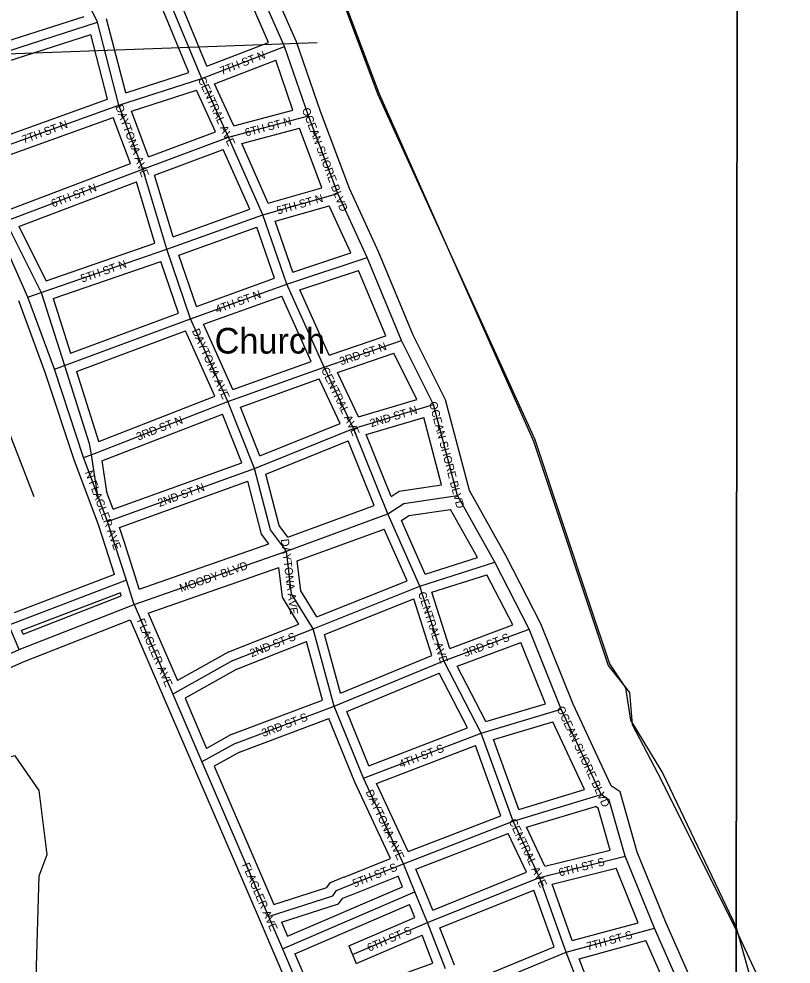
# Model space of a CAD drawing. Extents: x 457167 to 656239, y 1787309 to 1969297.
# Drawn here: x 614226 to 616636, y 1869724 to 1872675 of the extents above; entities that cross this region are included whole.
import ezdxf

# ---------------------------------------------------------------- set-up
doc = ezdxf.new("R2010")
doc.units = 0
for name, color, linetype in [('Level 1', 7, 'Continuous'), ('Level 22', 7, 'Continuous'), ('Level 23', 7, 'Continuous'), ('Level 31', 7, 'Continuous'), ('Level 32', 7, 'Continuous'), ('Level 34', 7, 'Continuous'), ('Level 5', 7, 'Continuous'), ('Level 57', 7, 'Continuous'), ('Level 63', 7, 'Continuous'), ('Level 7', 7, 'Continuous'), ('Level 8', 7, 'Continuous')]:
    doc.layers.add(name, color=color, linetype=linetype)

msp = doc.modelspace()

# ---------------------------------------------------------------- linework, layer by layer
at = {"layer": 'Level 1'}
msp.add_line((615156.706, 1872600.383), (611305.7, 1872459.876), dxfattribs=at)
at = {"layer": 'Level 22'}
for p, q in [((615055.016, 1872588.769), (614889.667, 1872964.947)), ((615129.865, 1872371.961), (615055.016, 1872588.769)), ((615221.233, 1872130.045), (615129.865, 1872371.961)), ((615312.647, 1871929.947), (615221.233, 1872130.045)), ((615420.545, 1871671.286), (615312.647, 1871929.947)), ((615520.234, 1871471.181), (615420.545, 1871671.286)), ((615594.696, 1871187.466), (615520.234, 1871471.181)), ((615711.243, 1870978.978), (615594.696, 1871187.466)), ((615060.91, 1871013.146), (615377.95, 1871129.521)), ((614585.675, 1870847.131), (615060.91, 1871013.146)), ((615819.2, 1870770.136), (615711.243, 1870978.978)), ((614226.92, 1870706.082), (614585.675, 1870847.131)), ((615918.839, 1870519.849), (615819.2, 1870770.136)), ((613943.273, 1870581.678), (614226.92, 1870706.082)), ((616043.281, 1870253.173), (615918.839, 1870519.849)), ((616209.565, 1869835.908), (616118.167, 1870061.095)), ((616323.838, 1869577.244), (616209.565, 1869835.908))]:
    msp.add_line(p, q, dxfattribs=at)
for points in [[(615377.95, 1871129.521), (615427.94, 1871162.557), (615594.696, 1871187.466)], [(616118.167, 1870061.095), (616068.4, 1870236.419), (616043.281, 1870253.173)]]:
    msp.add_lwpolyline(points, dxfattribs=at)
at = {"layer": 'Level 23'}
for p, q in [((615092.293, 1872603.367), (614926.286, 1872981.043)), ((615005.572, 1872601.849), (614863.518, 1872925.029)), ((615167.489, 1872385.557), (615092.293, 1872603.367)), ((615081.276, 1872390.126), (615027.469, 1872545.985)), ((615258.177, 1872145.44), (615167.489, 1872385.557)), ((615171.974, 1872147.252), (615101.65, 1872333.452)), ((615349.307, 1871945.962), (615258.176, 1872145.439)), ((615261.91, 1871944.741), (615194.914, 1872091.392)), ((615456.945, 1871687.923), (615349.307, 1871945.962)), ((615371.055, 1871686.022), (615286.15, 1871889.563)), ((615557.875, 1871485.324), (615456.945, 1871687.923)), ((615467.748, 1871486.829), (615395.873, 1871631.103)), ((615632.094, 1871202.541), (615557.875, 1871485.323)), ((615544.686, 1871220.44), (615489.501, 1871430.705)), ((615746.477, 1870997.926), (615632.095, 1871202.541)), ((615065.361, 1871057.39), (615334.78, 1871156.286)), ((615657.423, 1870993.275), (615573.267, 1871143.82)), ((615094.84, 1870982.99), (615365.949, 1871082.506)), ((614601.863, 1870895.157), (615006.18, 1871036.398)), ((615855.635, 1870786.757), (615746.477, 1870997.925)), ((614629.923, 1870820.217), (615036.918, 1870962.393)), ((615767.554, 1870782.933), (615686.569, 1870939.598)), ((614239.238, 1870753.906), (614545.527, 1870874.328)), ((614242.275, 1870669.138), (614573.564, 1870799.388)), ((615955.575, 1870535.716), (615855.635, 1870786.757)), ((615869.193, 1870536.404), (615792.796, 1870728.305)), ((613957.77, 1870544.356), (614242.275, 1870669.137)), ((616074.793, 1870280.236), (615955.575, 1870535.716)), ((615991.769, 1870268.966), (615892.894, 1870480.851)), ((616246.4, 1869851.515), (616156.051, 1870074.116)), ((616159.306, 1869853.371), (616090.344, 1870023.281)), ((616362.606, 1869588.472), (616246.4, 1869851.515)), ((616273.378, 1869592.475), (616182.773, 1869797.565))]:
    msp.add_line(p, q, dxfattribs=at)
for points in [[(615388.198, 1871184.239), (615413.275, 1871200.811), (615544.686, 1871220.439)], [(615419.75, 1871109.199), (615442.607, 1871124.304), (615573.267, 1871143.82)], [(616156.051, 1870074.115), (616102.857, 1870261.519), (616074.793, 1870280.236)], [(616071.125, 1870080.332), (616033.945, 1870211.318), (616025.994, 1870216.621)]]:
    msp.add_lwpolyline(points, dxfattribs=at)
at = {"layer": 'Level 31'}
for p, q in [((614796.55, 1872489.057), (614633.768, 1872882.688)), ((614471.575, 1872664.691), (614394.438, 1872823.321)), ((613979.505, 1872507.067), (614471.575, 1872664.691)), ((614538.101, 1872406.074), (614471.575, 1872664.691)), ((614796.55, 1872489.057), (615055.016, 1872588.769)), ((614538.101, 1872406.074), (614796.55, 1872489.057)), ((614879.707, 1872305.695), (614796.55, 1872489.057)), ((614079.109, 1872240.412), (614538.101, 1872406.074)), ((614612.649, 1872205.993), (614538.101, 1872406.074)), ((614879.707, 1872305.695), (615129.865, 1872371.961)), ((614612.649, 1872205.993), (614879.707, 1872305.695)), ((614987.619, 1872063.76), (614879.707, 1872305.695)), ((614184.52, 1872043.203), (614612.649, 1872205.993)), ((614687.459, 1871955.731), (614612.649, 1872205.993)), ((614987.619, 1872063.76), (615221.233, 1872130.045)), ((614687.459, 1871955.731), (614987.619, 1872063.76)), ((615062.15, 1871846.952), (614987.619, 1872063.76)), ((614253.615, 1871806.401), (614153.961, 1872031.602)), ((614184.52, 1872043.203), (614295.63, 1871820.536)), ((614295.63, 1871820.536), (614687.459, 1871955.731)), ((614761.988, 1871738.923), (614687.459, 1871955.731)), ((615062.15, 1871846.952), (615312.647, 1871929.947)), ((614761.988, 1871738.923), (615062.15, 1871846.952)), ((615178.636, 1871588.281), (615062.15, 1871846.952)), ((614253.615, 1871806.401), (614295.63, 1871820.536)), ((614336.724, 1871581.22), (614253.615, 1871806.401)), ((614295.63, 1871820.536), (614368.237, 1871592.821)), ((614368.237, 1871592.821), (614761.988, 1871738.923)), ((614878.155, 1871480.251), (614761.988, 1871738.923)), ((615178.636, 1871588.281), (615420.545, 1871671.286)), ((614336.724, 1871581.22), (614368.237, 1871592.821)), ((614427.733, 1871305.848), (614336.724, 1871581.22)), ((614878.155, 1871480.251), (615178.636, 1871588.281)), ((615270.061, 1871396.546), (615178.636, 1871588.281)), ((614451.288, 1871314.549), (614878.155, 1871480.251)), ((614961.287, 1871271.799), (614878.155, 1871480.251)), ((615270.061, 1871396.546), (615520.234, 1871471.181)), ((614961.287, 1871271.799), (615270.061, 1871396.546)), ((615377.95, 1871129.521), (615270.061, 1871396.546)), ((614427.733, 1871305.848), (614451.288, 1871314.549)), ((614470.241, 1871192.347), (614427.733, 1871305.848)), ((614451.288, 1871314.549), (614470.241, 1871192.347)), ((614502.599, 1871105.767), (614961.287, 1871271.799)), ((614502.599, 1871105.767), (614470.241, 1871192.347)), ((615477.613, 1870904.325), (615377.95, 1871129.521)), ((614525.746, 1871034.106), (614502.599, 1871105.767)), ((614561.577, 1870922.794), (614525.746, 1871034.106)), ((615477.613, 1870904.325), (615711.243, 1870978.978)), ((614561.577, 1870922.794), (614194.55, 1870782.481)), ((614585.675, 1870847.131), (614561.577, 1870922.794)), ((615144.007, 1870771.239), (615477.613, 1870904.325)), ((615552.132, 1870670.792), (615477.613, 1870904.325)), ((614585.675, 1870847.131), (614706.273, 1870567.001)), ((614226.92, 1870706.082), (614194.55, 1870782.481)), ((614893.802, 1870671.881), (615144.007, 1870771.239)), ((615210.242, 1870529.351), (615144.007, 1870771.239)), ((615552.132, 1870670.792), (615819.2, 1870770.136)), ((614893.802, 1870671.881), (614706.273, 1870567.001)), ((615210.242, 1870529.351), (615552.132, 1870670.792)), ((615668.661, 1870445.576), (615552.132, 1870670.792)), ((614706.273, 1870567.001), (614797.357, 1870355.265)), ((614901.47, 1870413.331), (615210.242, 1870529.351)), ((615301.633, 1870304.162), (615210.242, 1870529.351)), ((615668.661, 1870445.576), (615918.839, 1870519.849)), ((615301.633, 1870304.162), (615668.661, 1870445.576)), ((615768.274, 1870170.2), (615668.661, 1870445.576)), ((614901.47, 1870413.331), (614797.357, 1870355.265)), ((614797.357, 1870355.265), (614941.761, 1870019.473)), ((615426.072, 1870037.484), (615301.633, 1870304.162)), ((615768.274, 1870170.2), (616043.281, 1870253.173)), ((615426.072, 1870037.484), (615768.274, 1870170.2)), ((615851.131, 1869994.839), (615768.274, 1870170.2)), ((615851.131, 1869994.839), (616118.167, 1870061.095)), ((615252.58, 1869968.221), (615426.072, 1870037.484)), ((615461.931, 1869949.81), (615426.072, 1870037.484)), ((614941.761, 1870019.473), (615004.697, 1869873.056)), ((615217.564, 1869954.441), (615252.58, 1869968.221)), ((615500.965, 1869853.768), (615851.131, 1869994.839)), ((615934.245, 1869761.297), (615851.131, 1869994.839)), ((615004.697, 1869873.056), (615205.454, 1869937.728)), ((615048.367, 1869771.459), (615461.931, 1869949.81)), ((615205.454, 1869937.728), (615217.564, 1869954.441)), ((615500.965, 1869853.768), (615461.931, 1869949.81)), ((615004.697, 1869873.056), (615048.367, 1869771.459)), ((615267.3, 1869754.026), (615500.965, 1869853.768)), ((615557.445, 1869709.708), (615500.965, 1869853.768)), ((615934.245, 1869761.297), (616209.565, 1869835.908)), ((615048.367, 1869771.459), (615141.71, 1869554.166)), ((615592.35, 1869620.216), (615934.245, 1869761.297)), ((616042.135, 1869486.275), (615934.245, 1869761.297))]:
    msp.add_line(p, q, dxfattribs=at)
for points in [[(614368.237, 1871592.821), (614445.6, 1871349.827), (614451.288, 1871314.549)], [(615060.91, 1871013.146), (615011.03, 1871080.109), (614961.287, 1871271.799)], [(615144.007, 1870771.239), (615077.309, 1870879.675), (615060.91, 1871013.146)]]:
    msp.add_lwpolyline(points, dxfattribs=at)
at = {"layer": 'Level 32'}
for p, q in [((614813.08, 1872527.588), (614673.925, 1872864.084)), ((614756.388, 1872507.67), (614615.916, 1872847.349)), ((613993.671, 1872543.107), (614429.456, 1872682.701)), ((614559.228, 1872444.366), (614499.877, 1872675.091)), ((614020.864, 1872488.813), (614450.442, 1872626.419)), ((614502.247, 1872425.028), (614450.442, 1872626.419)), ((614813.079, 1872527.588), (615005.572, 1872601.849)), ((614836.998, 1872472.505), (615027.469, 1872545.985)), ((614559.227, 1872444.366), (614756.387, 1872507.67)), ((614577.18, 1872387.112), (614780.269, 1872452.32)), ((614839.115, 1872322.563), (614780.268, 1872452.32)), ((614896.55, 1872341.19), (614836.998, 1872472.505)), ((614101.22, 1872280.287), (614502.247, 1872425.029)), ((614630.279, 1872244.597), (614577.18, 1872387.111)), ((614896.55, 1872341.19), (615081.276, 1872390.126)), ((614127.865, 1872226.114), (614520.355, 1872367.774)), ((614574.131, 1872223.443), (614520.355, 1872367.775)), ((614921.465, 1872285.721), (615101.65, 1872333.452)), ((614630.28, 1872244.598), (614839.115, 1872322.563)), ((614649.427, 1872187.701), (614863.79, 1872267.729)), ((614947.058, 1872081.046), (614863.79, 1872267.729)), ((615004.43, 1872099.713), (614921.465, 1872285.721)), ((614201.58, 1872081.786), (614574.131, 1872223.442)), ((614707.123, 1871994.692), (614649.427, 1872187.701)), ((614226.16, 1872026.941), (614593.147, 1872166.481)), ((614650.474, 1871974.705), (614593.147, 1872166.481)), ((615004.43, 1872099.713), (615171.975, 1872147.252)), ((615026.29, 1872043.547), (615194.914, 1872091.392)), ((614707.124, 1871994.692), (614947.058, 1872081.046)), ((615080.875, 1871884.761), (615026.29, 1872043.547)), ((614226.161, 1872026.94), (614310.723, 1871857.478)), ((614725.442, 1871937.516), (614969.141, 1872025.224)), ((615024.165, 1871865.165), (614969.141, 1872025.225)), ((614310.723, 1871857.479), (614650.474, 1871974.705)), ((615080.875, 1871884.761), (615261.91, 1871944.741)), ((614333.113, 1871801.732), (614668.85, 1871917.573)), ((614724.097, 1871756.861), (614668.851, 1871917.573)), ((614780.464, 1871777.457), (614725.442, 1871937.516)), ((615103.164, 1871828.936), (615286.15, 1871889.563)), ((614780.465, 1871777.457), (615024.165, 1871865.165)), ((615194.763, 1871625.531), (615103.164, 1871828.936)), ((614333.113, 1871801.731), (614387.27, 1871631.881)), ((614802.625, 1871721.663), (615046.192, 1871809.323)), ((615137.962, 1871605.538), (615046.192, 1871809.324)), ((614308.4, 1871571.315), (614225.797, 1871795.126)), ((614387.27, 1871631.881), (614724.097, 1871756.862)), ((614894.142, 1871517.88), (614802.625, 1871721.664)), ((614405.505, 1871574.65), (614746.115, 1871701.034)), ((614837.842, 1871496.783), (614746.115, 1871701.033)), ((615194.763, 1871625.532), (615371.055, 1871686.022)), ((615220.195, 1871570.824), (615395.873, 1871631.102)), ((614894.142, 1871517.88), (615137.962, 1871605.538)), ((614399.431, 1871295.876), (614308.4, 1871571.315)), ((615286.088, 1871432.635), (615220.195, 1871570.824)), ((614917.522, 1871462.524), (615163.24, 1871550.865)), ((615229.256, 1871412.416), (615163.24, 1871550.865)), ((614475.002, 1871355.936), (614837.842, 1871496.784)), ((615286.089, 1871432.635), (615467.747, 1871486.829)), ((614484.63, 1871295.31), (614861.3, 1871441.526)), ((614921.944, 1871289.462), (614861.3, 1871441.526)), ((614977.989, 1871310.903), (614917.521, 1871462.524)), ((614977.989, 1871310.901), (615229.255, 1871412.416)), ((615310.225, 1871377.221), (615489.501, 1871430.705)), ((614996.94, 1871253.846), (615253.484, 1871357.492)), ((615334.78, 1871156.285), (615253.483, 1871357.491)), ((615388.198, 1871184.24), (615310.225, 1871377.221)), ((614442.146, 1871181.825), (614399.43, 1871295.876)), ((614484.63, 1871295.31), (614499.416, 1871199.976)), ((614520.305, 1871144.081), (614921.944, 1871289.462)), ((614540.051, 1871087.418), (614940.522, 1871232.376)), ((614474.259, 1871095.899), (614442.14, 1871181.845)), ((614520.305, 1871144.081), (614499.416, 1871199.976)), ((614497.198, 1871024.883), (614474.259, 1871095.899)), ((614554.295, 1871043.326), (614540.051, 1871087.418)), ((615494.143, 1870941.101), (615419.75, 1871109.198)), ((615437.578, 1870920.653), (615365.95, 1871082.506)), ((614590.134, 1870931.986), (614554.304, 1871043.297)), ((614524.307, 1870940.663), (614497.189, 1871024.912)), ((615494.143, 1870941.101), (615657.423, 1870993.275)), ((614524.307, 1870940.663), (614210.875, 1870820.84)), ((615515.31, 1870884.875), (615686.57, 1870939.599)), ((614601.863, 1870895.157), (614590.162, 1870931.897)), ((615156.335, 1870808.456), (615437.578, 1870920.653)), ((614542.628, 1870883.431), (614234.3, 1870765.56)), ((614545.526, 1870874.328), (614542.628, 1870883.431)), ((615571.15, 1870709.875), (615515.31, 1870884.875)), ((615180.022, 1870753.306), (615458.82, 1870864.527)), ((615515.16, 1870687.963), (615458.82, 1870864.527)), ((614573.565, 1870799.389), (614678.716, 1870555.137)), ((614629.923, 1870820.216), (614720.669, 1870609.426)), ((614239.237, 1870753.906), (614234.3, 1870765.559)), ((614880.886, 1870699.031), (615099.742, 1870785.94)), ((615571.151, 1870709.876), (615767.555, 1870782.933)), ((615230.195, 1870570.071), (615180.021, 1870753.306)), ((614906.715, 1870644.729), (615123.925, 1870730.984)), ((615174.081, 1870547.811), (615123.925, 1870730.984)), ((615594.346, 1870654.486), (615792.796, 1870728.305)), ((614880.886, 1870699.031), (614720.669, 1870609.426)), ((615230.196, 1870570.071), (615515.161, 1870687.963)), ((614906.715, 1870644.729), (614744.516, 1870554.015)), ((615683.905, 1870481.396), (615594.346, 1870654.486)), ((615249.245, 1870513.02), (615538.145, 1870632.539)), ((615626.627, 1870461.531), (615538.145, 1870632.539)), ((614678.714, 1870555.145), (614769.799, 1870343.41)), ((614744.515, 1870554.015), (614811.777, 1870397.657)), ((614888.816, 1870440.623), (615174.081, 1870547.811)), ((615683.905, 1870481.396), (615869.193, 1870536.405)), ((615318.347, 1870342.752), (615249.245, 1870513.02)), ((614914.122, 1870386.036), (615193.434, 1870490.986)), ((615274.122, 1870292.171), (615193.434, 1870490.986)), ((615707.692, 1870425.869), (615892.895, 1870480.851)), ((614888.816, 1870440.623), (614811.778, 1870397.657)), ((615318.348, 1870342.751), (615626.627, 1870461.53)), ((615786.816, 1870207.131), (615707.692, 1870425.869)), ((614914.122, 1870386.036), (614835.61, 1870342.248)), ((615342.409, 1870287.722), (615650.867, 1870406.571)), ((615730.087, 1870187.567), (615650.867, 1870406.571)), ((614769.797, 1870343.413), (614914.201, 1870007.621)), ((614835.61, 1870342.248), (614969.321, 1870031.324)), ((615385.458, 1870053.572), (615274.122, 1870292.171)), ((615441.39, 1870075.601), (615342.41, 1870287.722)), ((615786.816, 1870207.131), (615991.769, 1870268.966)), ((615810.273, 1870151.535), (616025.994, 1870216.621)), ((615441.39, 1870075.602), (615730.088, 1870187.567)), ((615867.757, 1870029.874), (615810.273, 1870151.535)), ((615465.405, 1870020.561), (615753.08, 1870132.129)), ((615810.418, 1870010.78), (615753.08, 1870132.129)), ((615867.756, 1870029.874), (616071.124, 1870080.332)), ((614969.324, 1870031.32), (615021.48, 1869909.981)), ((615241.456, 1869996.082), (615385.458, 1870053.572)), ((614914.199, 1870007.626), (614978.626, 1869857.737)), ((615198.416, 1869979.146), (615241.595, 1869996.136)), ((615263.703, 1869940.357), (615409.565, 1869998.59)), ((615423.019, 1869965.699), (615409.566, 1869998.591)), ((615489.699, 1869961.166), (615465.405, 1870020.561)), ((615517.495, 1869892.771), (615810.418, 1870010.78)), ((615890.499, 1869973.696), (616090.345, 1870023.281)), ((615064.068, 1869810.901), (615423.019, 1869965.7)), ((615186.916, 1869963.274), (615198.416, 1869979.146)), ((615953.199, 1869797.516), (615890.499, 1869973.696)), ((615021.48, 1869909.981), (615186.916, 1869963.274)), ((615236.71, 1869929.736), (615263.565, 1869940.303)), ((615517.495, 1869892.771), (615489.724, 1869961.105)), ((615539.743, 1869837.046), (615833.347, 1869955.33)), ((615896.408, 1869778.137), (615833.347, 1869955.33)), ((615045.28, 1869854.611), (615223.99, 1869912.181)), ((615087.755, 1869755.774), (615445.674, 1869910.126)), ((615223.99, 1869912.181), (615236.71, 1869929.736)), ((615462.07, 1869869.784), (615445.675, 1869910.126)), ((614978.626, 1869857.737), (615021.472, 1869758.055)), ((615045.28, 1869854.611), (615064.068, 1869810.901)), ((615255.521, 1869781.616), (615462.07, 1869869.784)), ((615953.198, 1869797.516), (616159.306, 1869853.37)), ((615585.376, 1869720.658), (615539.743, 1869837.046)), ((615279.078, 1869726.433), (615484.315, 1869814.041)), ((615518.247, 1869727.494), (615484.315, 1869814.041)), ((615974.396, 1869741.095), (616182.773, 1869797.565)), ((615255.521, 1869781.616), (615279.078, 1869726.433)), ((615609.183, 1869659.616), (615896.408, 1869778.138)), ((615021.47, 1869758.061), (615114.145, 1869542.326)), ((615087.755, 1869755.774), (615157.135, 1869594.266)), ((616059.76, 1869523.491), (615974.396, 1869741.095)), ((615294.229, 1869646.945), (615518.248, 1869727.494))]:
    msp.add_line(p, q, dxfattribs=at)
for points in [[(614405.505, 1871574.65), (614474.863, 1871356.804), (614475.002, 1871355.935)], [(615065.36, 1871057.39), (615038.594, 1871093.325), (614996.939, 1871253.846)], [(615006.18, 1871036.398), (614983.465, 1871066.894), (614940.522, 1871232.376)], [(615156.335, 1870808.456), (615106.288, 1870889.823), (615094.84, 1870982.99)], [(615099.743, 1870785.94), (615048.329, 1870869.526), (615036.918, 1870962.393)]]:
    msp.add_lwpolyline(points, dxfattribs=at)
at = {"layer": 'Level 5'}
for points in [[(612905.535, 1878220.299), (612930.405, 1878095.227), (613329.636, 1877261.166), (613487.7, 1876935.891), (613770.349, 1876202.001), (613820.27, 1876118.571), (614119.628, 1875384.651), (614460.568, 1874592.35), (614660.014, 1874008.611), (615159.077, 1872949.378), (615350.262, 1872440.641), (615832.625, 1871356.426), (616065.282, 1870655.916), (616131.874, 1870572.496), (616140.115, 1870472.424), (616231.657, 1870297.261), (616464.543, 1869830.206), (616464.765, 1869829.726)], [(614273.545, 1871182.996), (614082.329, 1871675.032), (613965.975, 1872008.616), (613916.065, 1872117.058), (613874.414, 1872142.098), (613640.93, 1872067.336)], [(616464.765, 1869829.726), (616689.139, 1869346.469), (616772.201, 1869079.605), (616996.757, 1868579.198), (617412.528, 1867586.725), (617512.271, 1867311.531), (617753.467, 1866786.084)]]:
    msp.add_lwpolyline(points, dxfattribs=at)
at = {"layer": 'Level 63'}
for points in [[(576611.219, 1832825.663), (616425.226, 1832761.92), (616473.71, 1878215.526), (576708.29, 1878279.4), (576611.219, 1832825.663)], [(616425.226, 1832761.92), (656239.136, 1832740.786), (656239.03, 1878194.373), (616473.71, 1878215.526), (616425.226, 1832761.92)]]:
    msp.add_lwpolyline(points, dxfattribs=at)
at = {"layer": 'Level 7'}
msp.add_lwpolyline([(614280.274, 1869682.472), (614288.972, 1869999.247), (614314.051, 1870065.908), (614289.23, 1870266.011), (614214.339, 1870374.442), (613864.114, 1870299.78), (613088.545, 1870025.531), (612996.784, 1869958.94), (612979.945, 1869800.547)], dxfattribs=at)
at = {"layer": 'Level 8'}
for points in [[(612954.764, 1878221.178), (612955.405, 1878219.799), (612971.406, 1878069.796), (613328.416, 1877267.786), (613486.42, 1876942.781), (613768.429, 1876208.771), (613809.43, 1876140.771), (613818.43, 1876125.771), (614109.438, 1875382.761), (614458.448, 1874590.75), (614657.454, 1874006.741), (615155.467, 1872946.727), (615346.472, 1872438.721), (615836.485, 1871361.706), (616007.49, 1870847.699), (616069.492, 1870661.696), (616119.494, 1870586.696)], [(616119.494, 1870586.696), (616135.495, 1870485.694), (616235.497, 1870319.691), (616464.503, 1869839.686), (616464.775, 1869838.715)], [(616464.775, 1869838.715), (616745.512, 1868837.671), (619996.599, 1860769.559)]]:
    msp.add_lwpolyline(points, dxfattribs=at)

# ---------------------------------------------------------------- texts
at = {"layer": 'Level 34'}
for s, height, rotation, p in [('7TH ST N', 25, 21.095419, (614859.17, 1872499.817)), ('CENTRAL AVE', 25, 294.394614, (614784.012, 1872486.441)), ('DAYTONA AVE', 25, 290.434292, (614526.549, 1872401.28)), ('OCEAN SHORE BLVD', 25, 290.690375, (615108.771, 1872392.436)), ('7TH ST N', 25, 19.845497, (614241.155, 1872285.61)), ('6TH ST N', 25, 14.836683, (614934.917, 1872307.389)), ('6TH ST N', 25, 20.818186, (614332.371, 1872086.049)), ('5TH ST N', 25, 15.840594, (615034.664, 1872064.115)), ('5TH ST N', 25, 19.035983, (614423.718, 1871851.508)), ('4TH ST N', 24.9992, 19.793575, (614844.291, 1871755.26)), ('DAYTONA AVE', 25, 294.183961, (614765.121, 1871701.436)), ('3RD ST N', 25, 18.938244, (615231.701, 1871593.275)), ('CENTRAL AVE', 25, 295.492936, (615168.535, 1871580.424)), ('OCEAN SHORE BLVD', 25, 284.705722, (615505.797, 1871476.948)), ('2ND ST N', 25, 16.611019, (615325.832, 1871400.141)), ('3RD ST N', 25, 21.215083, (614598.336, 1871358.222)), ('N FLAGLER AVE', 25, 290.491861, (614431.71, 1871259.742)), ('2ND ST N', 25, 19.898472, (614664.676, 1871151.141)), ('DAYTONA AVE', 25, 277.003875, (615043.741, 1871050.392)), ('MOODY BLVD', 25, 19.255539, (614732.414, 1870885.151)), ('CENTRAL AVE', 25, 287.697175, (615471.512, 1870882.327)), ('FLAGLER AVE', 25, 293.291928, (614593.768, 1870796.721)), ('2ND ST S', 25, 21.657972, (614952.825, 1870681.871)), ('3RD ST S', 25, 20.403922, (615618.733, 1870682.23)), ('OCEAN SHORE BLVD', 25, 295.015433, (615903.806, 1870522.506)), ('3RD ST S', 25, 20.593258, (614989.05, 1870432.886)), ('4TH ST S', 25, 21.071125, (615418.223, 1870335.689)), ('DAYTONA AVE', 25, 295.014608, (615307.576, 1870261.866)), ('CENTRAL AVE', 25, 295.290514, (615754.2, 1870170.726)), ('6TH ST S', 25, 13.934267, (615914.294, 1869997.631)), ('FLAGLER AVE', 25, 293.259567, (614921.82, 1870034.214)), ('5TH ST S', 25, 21.763011, (615273.32, 1869963.041)), ('6TH ST S', 25, 23.115367, (615319.518, 1869762.726)), ('7TH ST S', 25, 15.162533, (616001.608, 1869766.602))]:
    msp.add_text(s, height=height, rotation=rotation, dxfattribs=at).set_placement(p)
at = {"layer": 'Level 57'}
msp.add_text('Church', height=80, dxfattribs=at).set_placement((614836.94, 1871630.327))

doc.saveas('drawing.dxf')
